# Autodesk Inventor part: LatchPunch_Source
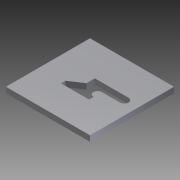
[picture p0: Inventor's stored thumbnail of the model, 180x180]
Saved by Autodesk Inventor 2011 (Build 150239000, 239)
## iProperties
Created: 2007-02
Part Number: LatchPunch_Source
Material: Default
Document SubType Name: Sheet Metal
Designer: Autodesk, Inc.
Mass: 0.206187 g
Surface Area: 4.97142 cm^2
Volume: 0.206187 cm^3
Density: 1 g/cm^3
Sheet Metal Rule: 1 mm
Author: Autodesk, Inc.
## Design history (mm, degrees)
node "Face1"
  sketch "Sketch1"
    geometry: L1 (-7.5, 7.5)-(7.5, 7.5); L2 (7.5, 7.5)-(7.5, -7.5); L3 (7.5, -7.5)-(-7.5, -7.5); L4 (-7.5, -7.5)-(-7.5, 7.5); L5 (-7.5, 7.5)-(7.5, -7.5); 2 further points
    constraints: 10 end point, 2 parallel, 1 coincident, 1 horizontal, 1 midpoint, 1 perpendicular
    dimensions: "d14" = 15 distance of L2.end L3.end; "d15" = 15 distance of L1.end L2.end (= d14)
sketch "Sketch2"
  geometry: L1 (-3.117, -1.262)-(-0.867, 0.238); L2 (-0.867, 0.238)-(-0.867, 1.738); L3 (-0.867, 1.738)-(5.133, 1.738); L4 (5.133, 0.238)-(1.883, 0.238); L5 (1.883, -1.262)-(1.883, -2.062); L6 (1.883, -2.062)-(-3.117, -2.062); L7 (-3.117, -2.062)-(-3.117, -1.262); L8 (-3.117, -1.262)-(1.883, -1.262); A1 r 0.75 centre (5.133, 0.988) between (5.133, 0.238) and (5.133, 1.738); A2 r 0.75 centre (1.883, -0.512) between (1.883, 0.238) and (1.883, -1.262); 1 further point
  constraints: 16 end point, 4 perpendicular, 4 point on circle, 3 tangent, 2 centre point, 2 parallel, 1 equal radius, 1 point on line
  dimensions: "d7" = 3.8 distance between parallel lines of L3 L6; "d8" = 0.8 distance from line of L1.start L6; "d9" = 2.3 distance from line of L1.end L6; "d10" = 2.25 distance from line of L1.end L7; "d11" = 9 dimension on A1 L7; "d12" = 5 distance from line of L7 A2.centre; "d13" = 0.75 radius of A2; "d16" = 5 distance of L5.end L6.end; "d17" = 4.5 distance from line of point (1.383, -0.375) L7 (= 0.5 x d11); "d18" = 1.68678 distance from line of point (1.383, -0.375) L6; "d19" = 0.88678 distance from line of point (1.383, -0.375) L8 (derived)
cut "Cut1" sketch "Sketch2" dims "d20" = 1 (= Thickness), "d21" = 0
body "Solid1"
face "Plate1" dims "Thickness" = 1
other parameters: "BendRadius" = 0.5, "BendReliefWidth" = 1 (= Thickness), "BendReliefDepth" = 0.5 (= 0.5 x Thickness), "CornerReliefSize" = 4 (= 4 x Thickness), "SeamGap" = 0.01, "MinimumRemnant" = 2 (= 2 x Thickness), "TransitionRadius" = 0.5 (= BendRadius), "JacobiRadiusSize" = 1 (= Thickness), "d0" = 0.5 (= BendRadius), "GapSize" = 1 (= Thickness)
